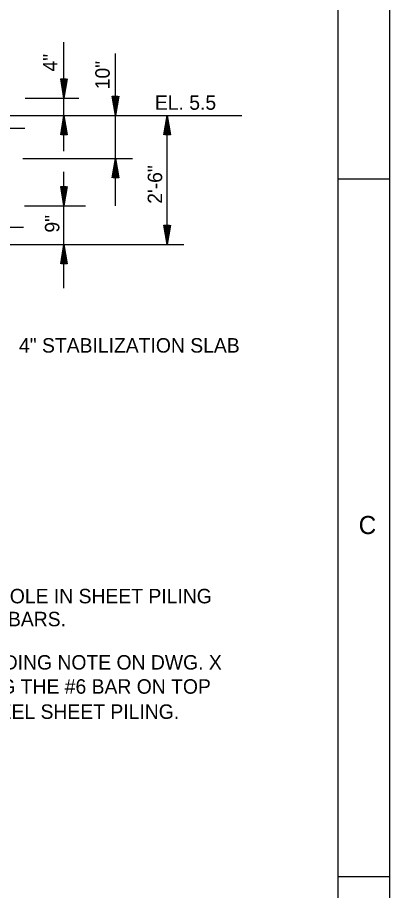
# Model space of a CAD drawing. Extents: x -11983 to -11903, y -13969.5 to -13913.5.
# Drawn here: x -11910.22 to -11903.01, y -13941.75 to -13924.86 of the extents above; entities that cross this region are included whole.
import ezdxf

# ---------------------------------------------------------------- set-up
doc = ezdxf.new("R2010")
doc.units = 0
doc.layers.add('Level 1', color=7, linetype='Continuous')
doc.layers.add('Level 3', color=7, linetype='Continuous')

msp = doc.modelspace()

# ---------------------------------------------------------------- linework, layer by layer
at = {"layer": 'Level 1'}
for p, q in [((-11904.012, -13927.981), (-11903.012, -13927.981)), ((-11904.012, -13941.481), (-11903.012, -13941.481))]:
    msp.add_line(p, q, dxfattribs=at)
for points in [[(-11983.012, -13913.481), (-11903.012, -13913.481), (-11903.012, -13969.481), (-11983.012, -13969.481)], [(-11980.012, -13914.481), (-11904.012, -13914.481), (-11904.012, -13968.481), (-11980.012, -13968.481)]]:
    msp.add_lwpolyline(points, close=True, dxfattribs=at)
at = {"layer": 'Level 3'}
for p, q in [((-11909.319, -13926.419), (-11909.319, -13925.332)), ((-11908.319, -13926.752), (-11908.319, -13925.551)), ((-11909.319, -13926.315), (-11909.319, -13926.315)), ((-11909.319, -13926.83), (-11909.319, -13926.352)), ((-11910.071, -13926.419), (-11909.032, -13926.419)), ((-11909.319, -13926.419), (-11909.319, -13926.419)), ((-11908.319, -13926.648), (-11908.319, -13926.648)), ((-11912.101, -13926.752), (-11905.873, -13926.752)), ((-11909.319, -13926.752), (-11909.319, -13926.752)), ((-11909.319, -13927.442), (-11909.319, -13926.752)), ((-11909.319, -13926.856), (-11909.319, -13926.856)), ((-11908.319, -13927.701), (-11908.319, -13926.752)), ((-11908.319, -13926.752), (-11908.319, -13926.752)), ((-11907.319, -13929.25), (-11907.319, -13926.752)), ((-11907.319, -13926.752), (-11907.319, -13926.752)), ((-11907.319, -13926.856), (-11907.319, -13926.856)), ((-11912.056, -13927.002), (-11910.076, -13927.002)), ((-11910.115, -13927.585), (-11907.987, -13927.585)), ((-11908.319, -13928.501), (-11908.319, -13927.585)), ((-11908.319, -13927.585), (-11908.319, -13927.585)), ((-11908.319, -13927.689), (-11908.319, -13927.689)), ((-11909.319, -13928.501), (-11909.319, -13927.842)), ((-11910.082, -13928.501), (-11908.901, -13928.501)), ((-11909.319, -13928.397), (-11909.319, -13928.397)), ((-11909.319, -13929.25), (-11909.319, -13928.501)), ((-11909.319, -13928.501), (-11909.319, -13928.501)), ((-11912.056, -13928.917), (-11910.098, -13928.917)), ((-11907.319, -13929.146), (-11907.319, -13929.146)), ((-11912.057, -13929.25), (-11906.994, -13929.25)), ((-11909.319, -13930.094), (-11909.319, -13929.25)), ((-11909.319, -13929.25), (-11909.319, -13929.25)), ((-11909.319, -13929.354), (-11909.319, -13929.354)), ((-11907.319, -13929.25), (-11907.319, -13929.25))]:
    msp.add_line(p, q, dxfattribs=at)
for points in [[(-11909.257, -13926.045), (-11909.319, -13926.419), (-11909.381, -13926.045), (-11909.275, -13926.045), (-11909.319, -13926.315), (-11909.361, -13926.061), (-11909.293, -13926.061), (-11909.319, -13926.215), (-11909.341, -13926.077), (-11909.313, -13926.077), (-11909.319, -13926.111)], [(-11908.257, -13926.378), (-11908.319, -13926.752), (-11908.381, -13926.378), (-11908.275, -13926.378), (-11908.319, -13926.648), (-11908.361, -13926.394), (-11908.293, -13926.394), (-11908.319, -13926.548), (-11908.341, -13926.41), (-11908.313, -13926.41), (-11908.319, -13926.444)], [(-11909.381, -13927.126), (-11909.319, -13926.752), (-11909.257, -13927.126), (-11909.363, -13927.126), (-11909.319, -13926.856), (-11909.277, -13927.11), (-11909.345, -13927.11), (-11909.319, -13926.956), (-11909.297, -13927.094), (-11909.325, -13927.094), (-11909.319, -13927.06)], [(-11907.381, -13927.126), (-11907.319, -13926.752), (-11907.257, -13927.126), (-11907.363, -13927.126), (-11907.319, -13926.856), (-11907.277, -13927.11), (-11907.345, -13927.11), (-11907.319, -13926.956), (-11907.297, -13927.094), (-11907.325, -13927.094), (-11907.319, -13927.06)], [(-11908.381, -13927.959), (-11908.319, -13927.585), (-11908.257, -13927.959), (-11908.363, -13927.959), (-11908.319, -13927.689), (-11908.277, -13927.943), (-11908.345, -13927.943), (-11908.319, -13927.789), (-11908.297, -13927.927), (-11908.325, -13927.927), (-11908.319, -13927.893)], [(-11909.257, -13928.127), (-11909.319, -13928.501), (-11909.381, -13928.127), (-11909.275, -13928.127), (-11909.319, -13928.397), (-11909.361, -13928.143), (-11909.293, -13928.143), (-11909.319, -13928.297), (-11909.341, -13928.159), (-11909.313, -13928.159), (-11909.319, -13928.193)], [(-11907.257, -13928.876), (-11907.319, -13929.25), (-11907.381, -13928.876), (-11907.275, -13928.876), (-11907.319, -13929.146), (-11907.361, -13928.892), (-11907.293, -13928.892), (-11907.319, -13929.046), (-11907.341, -13928.908), (-11907.313, -13928.908), (-11907.319, -13928.942)], [(-11909.381, -13929.624), (-11909.319, -13929.25), (-11909.257, -13929.624), (-11909.363, -13929.624), (-11909.319, -13929.354), (-11909.277, -13929.608), (-11909.345, -13929.608), (-11909.319, -13929.454), (-11909.297, -13929.592), (-11909.325, -13929.592), (-11909.319, -13929.558)]]:
    msp.add_lwpolyline(points, dxfattribs=at)

# ---------------------------------------------------------------- texts
at = {"layer": 'Level 1'}
msp.add_text('C', height=0.351, dxfattribs=at).set_placement((-11903.61, -13934.854))
at = {"layer": 'Level 3'}
for s, p in [('4"', (-11909.443, -13925.903)), ('10"', (-11908.431, -13926.247)), ('2\'-6"', (-11907.416, -13928.462)), ('9"', (-11909.406, -13929.02))]:
    msp.add_text(s, height=0.28, rotation=90, dxfattribs=at).set_placement(p)
for s, p in [('EL. 5.5', (-11907.557, -13926.643)), ('4" STABILIZATION SLAB', (-11910.188, -13931.342)), ('BURN 2" O HOLE IN SHEET PILING', (-11912.642, -13936.194)), ('TO PASS REBARS.', (-11912.649, -13936.638)), ('2. SEE BONDING NOTE ON DWG. X', (-11912.565, -13937.476)), ('REGARDING THE #6 BAR ON TOP', (-11912.527, -13937.943)), ('OF THE STEEL SHEET PILING.', (-11912.538, -13938.43))]:
    msp.add_text(s, height=0.28, dxfattribs=at).set_placement(p)

doc.saveas('drawing.dxf')
